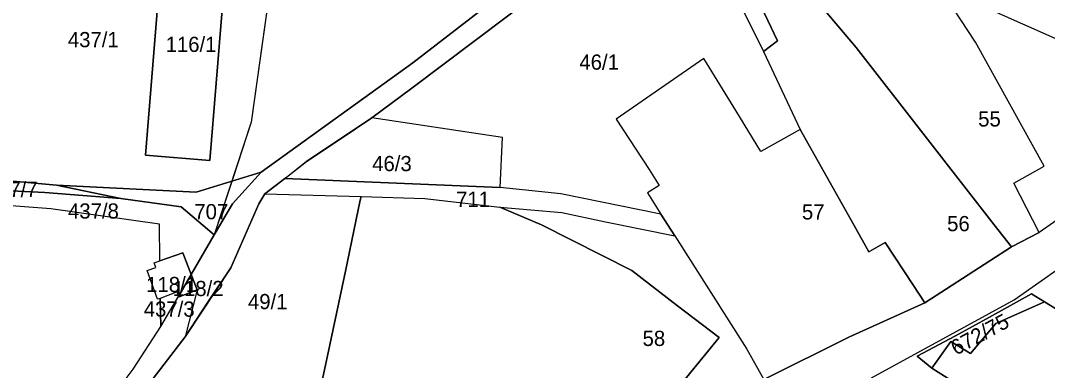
# Model space of a CAD drawing. Extents: x -629983 to -626385, y -1072828 to -1067897.
# Drawn here: x -627674 to -627471.3, y -1070463.2 to -1070394.2 of the extents above; entities that cross this region are included whole.
import ezdxf

# ---------------------------------------------------------------- set-up
doc = ezdxf.new("R2010")
doc.units = 0
for name, color, linetype in [('Parcela nároku', 7, 'Continuous'), ('Parcelní číslo', 7, 'Continuous'), ('Plocha PÚ', 7, 'Continuous'), ('Vnitřní obvod_šetřený', 7, 'Continuous')]:
    doc.layers.add(name, color=color, linetype=linetype)

msp = doc.modelspace()

# ---------------------------------------------------------------- linework, layer by layer
at = {"layer": 'Parcela nároku'}
for points in [[(-627675.73, -1070497.41), (-627670.84, -1070489.21), (-627664.39, -1070479.79), (-627651.75, -1070462.96), (-627646.33, -1070454.56), (-627642.78, -1070448.49), (-627642.71, -1070448.68), (-627639.15, -1070447.3), (-627640.32, -1070444.28), (-627635.77, -1070436.5), (-627632.18, -1070430.36), (-627626.49, -1070424.12), (-627596.54, -1070402.58), (-627580.46, -1070390.03), (-627569.41, -1070380), (-627553.68, -1070362.8), (-627551.79, -1070360), (-627538.05, -1070339.59), (-627535.93, -1070336.45), (-627527.1, -1070326.43), (-627512.99, -1070294.4), (-627506.01, -1070282.58), (-627504.39, -1070279.94), (-627482.04, -1070235.24)], [(-627505.98, -1070464.68), (-627477.81, -1070449.31), (-627458.09, -1070435.4), (-627450.22, -1070429.04), (-627437.75, -1070413.5), (-627426.3, -1070400.46), (-627415.46, -1070387.81), (-627412.15, -1070383.27), (-627394.72, -1070360.62), (-627388.2, -1070352.2), (-627383.11, -1070345.19), (-627377.74, -1070338.6), (-627373.15, -1070332.69), (-627367.96, -1070325.83), (-627354.53, -1070308.48), (-627342.39, -1070292.8), (-627324.47, -1070271.16), (-627314.49, -1070262.38), (-627293.26, -1070245.57)], [(-627312.14, -1070249.25), (-627330.99, -1070266.01), (-627341.32, -1070276.32), (-627349.34, -1070287.13), (-627352.3, -1070292.06), (-627363.34, -1070304.23), (-627367.77, -1070308.37), (-627368.12, -1070308.7), (-627371.73, -1070313.39), (-627379.18, -1070322.46), (-627382.5, -1070326.5), (-627395.65, -1070343.56), (-627403.01, -1070355.05), (-627411.51, -1070366.62), (-627414.33, -1070370.56), (-627419.9, -1070377.83), (-627432.7, -1070392.58), (-627443.88, -1070409.16), (-627459.21, -1070426.46), (-627472.89, -1070436.01), (-627478.35, -1070438.88), (-627495.48, -1070449.89), (-627510.48, -1070456.69), (-627527.27, -1070465.04)], [(-627693.61, -1070374.29), (-627645.62, -1070375.32), (-627649.31, -1070420.79), (-627636.65, -1070421.82), (-627632.91, -1070375.97), (-627604.25, -1070378.04), (-627569.41, -1070380), (-627580.46, -1070390.03), (-627596.54, -1070402.58), (-627626.49, -1070424.12), (-627639.33, -1070428.04), (-627666.89, -1070426.71), (-627676.98, -1070425.76)], [(-627571.72, -1070388.7), (-627596.73, -1070407.55), (-627604.65, -1070413.41), (-627617.53, -1070422.04), (-627621.49, -1070425.14), (-627621.8, -1070425.36), (-627625.75, -1070428.38), (-627626.98, -1070430.39), (-627632.51, -1070442.99), (-627641.51, -1070456.58), (-627647.83, -1070464.84)], [(-627647.83, -1070464.84), (-627641.51, -1070456.58), (-627632.51, -1070442.99), (-627626.98, -1070430.39), (-627625.75, -1070428.38), (-627606.73, -1070428.95), (-627606.92, -1070429.66), (-627609.85, -1070443.64), (-627612.95, -1070458.16), (-627614.01, -1070463.13), (-627614.82, -1070467.07)], [(-627543.71, -1070466.09), (-627536.07, -1070456.71), (-627544.3, -1070450.49), (-627553.34, -1070443.49), (-627571.18, -1070434.53), (-627579.4, -1070431.05), (-627567.11, -1070432.05), (-627558.53, -1070433.94), (-627544.83, -1070436.71), (-627530.63, -1070459.01), (-627527.27, -1070465.04)], [(-627505.98, -1070464.68), (-627477.81, -1070449.31), (-627458.09, -1070435.4)], [(-627468.6, -1070451.68), (-627471.87, -1070449.68), (-627474.41, -1070448.12), (-627482.7, -1070452.72), (-627489.41, -1070456.38), (-627496.99, -1070460.41), (-627494.07, -1070462.79), (-627490.34, -1070465.18)]]:
    msp.add_lwpolyline(points, dxfattribs=at)
for points in [[(-627523.07, -1070373.63), (-627526.06, -1070381.6), (-627512.05, -1070389.37), (-627515.53, -1070391.8), (-627509.05, -1070399.5), (-627481.79, -1070434.49), (-627478.35, -1070438.88), (-627472.89, -1070436.01), (-627477.9, -1070426.3), (-627471.88, -1070422.95), (-627485.49, -1070398.49), (-627492.61, -1070387.47), (-627503.17, -1070382.49)], [(-627645.62, -1070375.32), (-627632.91, -1070375.97), (-627636.65, -1070421.82), (-627649.31, -1070420.79)], [(-627550.24, -1070428.21), (-627547.59, -1070432.38), (-627567.3, -1070428.39), (-627579.32, -1070427.13), (-627578.85, -1070417.27), (-627604.65, -1070413.41), (-627596.73, -1070407.55), (-627571.72, -1070388.7), (-627561.95, -1070380.18), (-627538.65, -1070380.92), (-627536.65, -1070381.47), (-627527.29, -1070400.28), (-627520.07, -1070415.67), (-627527.83, -1070420.03), (-627532.81, -1070411.95), (-627539.12, -1070401.72), (-627556.41, -1070413.63), (-627549.89, -1070423.61), (-627547.92, -1070426.74)], [(-627531.55, -1070383.49), (-627534.08, -1070382.18), (-627536.65, -1070381.47), (-627527.29, -1070400.28), (-627524.58, -1070398.23)], [(-627482.22, -1070382.97), (-627489.96, -1070382.08), (-627491.48, -1070381.91), (-627503.17, -1070382.49), (-627492.61, -1070387.47), (-627443.88, -1070409.16), (-627432.7, -1070392.58), (-627447.43, -1070389.39), (-627476.87, -1070383.66), (-627478.87, -1070383.4)], [(-627515.53, -1070391.8), (-627531.55, -1070383.49), (-627524.58, -1070398.23), (-627527.29, -1070400.28), (-627520.07, -1070415.67), (-627509.42, -1070434.62), (-627506.5, -1070439.81), (-627503.29, -1070437.99), (-627497.86, -1070446.25), (-627495.48, -1070449.89), (-627478.35, -1070438.88), (-627481.79, -1070434.49), (-627509.05, -1070399.5)], [(-627492.61, -1070387.47), (-627443.88, -1070409.16), (-627459.21, -1070426.46), (-627472.89, -1070436.01), (-627477.9, -1070426.3), (-627471.88, -1070422.95), (-627485.49, -1070398.49)], [(-627532.81, -1070411.95), (-627539.12, -1070401.72), (-627556.41, -1070413.63), (-627549.89, -1070423.61), (-627547.92, -1070426.74), (-627550.24, -1070428.21), (-627547.59, -1070432.38), (-627544.83, -1070436.71), (-627530.63, -1070459.01), (-627527.27, -1070465.04), (-627510.48, -1070456.69), (-627495.48, -1070449.89), (-627497.86, -1070446.25), (-627503.29, -1070437.99), (-627506.5, -1070439.81), (-627509.42, -1070434.62), (-627520.07, -1070415.67), (-627527.83, -1070420.03)], [(-627617.53, -1070422.04), (-627621.49, -1070425.14), (-627621.8, -1070425.36), (-627579.32, -1070427.13), (-627578.85, -1070417.27), (-627604.65, -1070413.41)], [(-627666.89, -1070426.71), (-627654.23, -1070429.31), (-627669.22, -1070428.12), (-627679.96, -1070427.62), (-627679.79, -1070425.58), (-627676.98, -1070425.76)], [(-627666.89, -1070426.71), (-627639.33, -1070428.04), (-627626.49, -1070424.12), (-627632.18, -1070430.36), (-627635.77, -1070436.5), (-627642.29, -1070430.98), (-627654.23, -1070429.31)], [(-627621.8, -1070425.36), (-627625.75, -1070428.38), (-627606.73, -1070428.95), (-627594.2, -1070429.32), (-627579.4, -1070431.05), (-627567.11, -1070432.05), (-627558.53, -1070433.94), (-627544.83, -1070436.71), (-627547.59, -1070432.38), (-627567.3, -1070428.39), (-627579.32, -1070427.13)], [(-627669.22, -1070428.12), (-627654.23, -1070429.31), (-627642.29, -1070430.98), (-627635.77, -1070436.5), (-627640.32, -1070444.28), (-627641.98, -1070440), (-627646.48, -1070441.6), (-627646.58, -1070434.36), (-627668.03, -1070431.32), (-627680.2, -1070430.46), (-627679.96, -1070427.62)], [(-627647.27, -1070442.94), (-627647.6, -1070442), (-627646.48, -1070441.6), (-627646.58, -1070434.36), (-627668.03, -1070431.32), (-627680.2, -1070430.46), (-627681.82, -1070449.47), (-627697.43, -1070448.14), (-627695.87, -1070429.41), (-627715.32, -1070428.36), (-627717.24, -1070475.16), (-627711.57, -1070475.61), (-627664.39, -1070479.79), (-627651.75, -1070462.96), (-627646.33, -1070454.56), (-627646.47, -1070449.01), (-627646.98, -1070449.19), (-627648.99, -1070443.55)], [(-627606.73, -1070428.95), (-627594.2, -1070429.32), (-627579.4, -1070431.05), (-627571.18, -1070434.53), (-627553.34, -1070443.49), (-627544.3, -1070450.49), (-627536.07, -1070456.71), (-627543.71, -1070466.09), (-627553.62, -1070475.66), (-627573.23, -1070471.4), (-627603.04, -1070465.37), (-627603.79, -1070468.78), (-627614.82, -1070467.07), (-627614.01, -1070463.13), (-627612.95, -1070458.16), (-627609.85, -1070443.64), (-627606.92, -1070429.66)], [(-627647.6, -1070442), (-627646.48, -1070441.6), (-627641.98, -1070440), (-627640.32, -1070444.28), (-627642.78, -1070448.49), (-627643.06, -1070447.77), (-627643.39, -1070447.89), (-627646.47, -1070449.01), (-627646.98, -1070449.19), (-627648.99, -1070443.55), (-627647.27, -1070442.94)], [(-627640.32, -1070444.28), (-627639.15, -1070447.3), (-627642.71, -1070448.68), (-627642.78, -1070448.49)], [(-627643.06, -1070447.77), (-627643.39, -1070447.89), (-627646.47, -1070449.01), (-627646.33, -1070454.56), (-627642.78, -1070448.49)], [(-627496.99, -1070460.41), (-627489.41, -1070456.38), (-627482.7, -1070452.72), (-627474.41, -1070448.12), (-627471.87, -1070449.68), (-627481.47, -1070453.96), (-627486.45, -1070459.89), (-627490.34, -1070457.51), (-627494.07, -1070462.79)], [(-627486.45, -1070459.89), (-627481.47, -1070453.96), (-627471.87, -1070449.68), (-627468.6, -1070451.68), (-627466.14, -1070449.57), (-627464.43, -1070452.22), (-627461.8, -1070450.47), (-627463.51, -1070447.82), (-627462.02, -1070446.46), (-627455.66, -1070453.56), (-627455.61, -1070453.64), (-627450.18, -1070461.9), (-627448.86, -1070466.92), (-627447.15, -1070471.57), (-627450.35, -1070481.39), (-627458.28, -1070480.75), (-627471.12, -1070477.13), (-627490.34, -1070465.18), (-627494.07, -1070462.79), (-627490.34, -1070457.51)]]:
    msp.add_lwpolyline(points, close=True, dxfattribs=at)
at = {"layer": 'Plocha PÚ'}
msp.add_lwpolyline([(-627623.07, -1070375.88), (-627628.47, -1070414.25), (-627635.77, -1070436.5), (-627640.32, -1070444.28), (-627639.15, -1070447.3), (-627641.51, -1070456.58), (-627637.01, -1070449.78), (-627632.51, -1070442.99), (-627626.98, -1070430.39), (-627625.75, -1070428.38), (-627621.8, -1070425.36), (-627617.53, -1070422.04), (-627611.09, -1070417.72), (-627604.65, -1070413.41), (-627596.73, -1070407.55), (-627584.22, -1070398.12), (-627571.72, -1070388.7)], dxfattribs=at)
at = {"layer": 'Vnitřní obvod_šetřený'}
msp.add_lwpolyline([(-627620.86, -1070362.17), (-627623.07, -1070375.88), (-627625.77, -1070395.06), (-627628.47, -1070414.25), (-627632.12, -1070425.38), (-627635.77, -1070436.5), (-627640.32, -1070444.28), (-627639.15, -1070447.3), (-627641.51, -1070456.58), (-627632.51, -1070442.99), (-627626.98, -1070430.39), (-627625.75, -1070428.38), (-627621.8, -1070425.36), (-627617.53, -1070422.04), (-627604.65, -1070413.41), (-627596.73, -1070407.55), (-627571.72, -1070388.7)], dxfattribs=at)

# ---------------------------------------------------------------- texts
at = {"layer": 'Parcelní číslo'}
for s, p in [('437/1', (-627664.66, -1070399.47)), ('116/1', (-627645.36, -1070400.4)), ('46/1', (-627563.67, -1070403.9)), ('55', (-627484.93, -1070415.12)), ('46/3', (-627604.58, -1070423.92)), ('437/7', (-627680.68, -1070429.02)), ('711', (-627588.01, -1070430.97)), ('437/8', (-627664.63, -1070433.28)), ('707', (-627639.7, -1070433.41)), ('57', (-627519.73, -1070433.46)), ('56', (-627491.06, -1070435.77)), ('118/1', (-627649.2, -1070447.78)), ('118/2', (-627643.96, -1070448.57)), ('49/1', (-627629.1, -1070451.15)), ('437/3', (-627649.67, -1070452.63)), ('58', (-627551.19, -1070458.41))]:
    msp.add_text(s, height=3, dxfattribs=at).set_placement(p)
msp.add_text('672/75', height=3, rotation=28.2704, dxfattribs=at).set_placement((-627489.31, -1070460.33))

doc.saveas('drawing.dxf')
